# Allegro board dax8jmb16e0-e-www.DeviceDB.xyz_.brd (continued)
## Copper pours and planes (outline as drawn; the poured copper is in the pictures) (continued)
N27265684 on TOP (solid shape): 190.56,30.46 190.56,29.33 190.51,29.28 190.51,28.94 190.5,28.93 190.48,28.81 190.5,28.68 190.51,28.68 190.51,28.33 190.36,28.17 188.7,28.17 188.43,28.45 188.43,30.46 188.44,30.47 188.55,30.5 188.61,30.4 188.61,29.8 188.81,29.8 188.81,30.54 188.83,30.57 188.87,30.59 189.09,30.59 189.11,30.61 190.41,30.61
N27267906 on BOTTOM (solid shape): 14.23,114.97 14.23,113.46 14.67,113.02 14.67,112.52 14.23,112.09 14.23,111.44 14.99,110.67 14.99,109.66 14.89,109.56 14.23,109.56 14.03,109.76 14.03,110.22 12.63,111.61 12.63,111.72 12.63,112.02 13.15,112.54 13.15,113.33 13.1,113.38 12.72,113.38 12.63,113.47 12.63,114.05 12.71,114.13 13.06,114.13 13.32,114.38 13.32,115.02 13.5,115.19 14,115.19
N27303100 on TOP (solid shape): 153.6,34.3 153.6,34.25 153.63,34.23 153.63,33.69 153.68,33.63 153.68,33.51 153.71,33.4 153.82,33.31 153.83,33.28 153.83,32.16 153.75,32.09 153.7,32.07 153.67,32.12 153.67,32.85 153.47,32.85 153.47,32.11 153.45,32.07 153.42,32.06 152.36,32.06 151.7,31.4 151.7,31.34 151.5,31.15 150.76,31.15 150.63,31.27 149.84,31.27 149.67,31.45 149.67,32.34 150.1,32.77 151.24,32.77 151.8,33.33 151.8,34.04 151.65,34.19 151.65,35.36 151.71,35.43 152.47,35.43
N27303319 on TOP (solid shape): 157.68,34.66 157.68,33.81 158,33.5 158,31.55 157.92,31.48 157.48,31.48 157.24,31.71 157.24,32.1 157.06,32.29 156.57,32.29 156.32,32.03 156.22,32.04 156.17,32.03 155.72,32.03 155.68,32.05 155.67,32.09 155.67,32.85 155.47,32.85 155.47,32.09 155.45,32.05 155.42,32.03 155.33,32.03 155.28,32.09 155.28,33.2 155.76,33.69 156.5,33.69 156.76,33.95 156.76,34.66 156.93,34.83 157.51,34.83
N30957248 on TOP (solid shape): 34.1,125.36 34.1,124.41 33.96,124.28 32.62,124.28 31.93,123.6 31.32,123.6 31.2,123.71 31.2,124.36 32.24,125.41 32.24,125.41 32.39,125.55 33.9,125.55
N31445230 on BOTTOM (solid shape): 223.78,74.94 223.78,73.97 223.43,73.61 223.43,72.04 224.07,71.39 224.07,70.87 224.38,70.57 224.38,70.4 224.39,70.39 224.39,68.47 224.39,62.01 224.16,61.78 221.55,61.78 221.39,61.93 221.39,63.82 221.46,63.96 221.47,64.12 221.47,64.13 221.48,64.15 221.83,64.5 223.43,64.5 223.76,64.83 223.76,69.75 223.63,69.88 223.63,70.52 223.32,70.83 223.32,70.99 223.25,71.36 222.89,71.47 222.89,71.96 222.91,72 223.01,72.14 223.04,72.31 223.04,72.54 223.03,72.67 222.97,72.78 222.96,72.81 222.97,72.84 223.04,73.12 222.91,73.39 222.89,73.42 222.89,73.94 223.12,74.17 223.12,74.41 223.12,74.96 223.25,75.09 223.63,75.09
N31667829 on TOP (solid shape): 162.67,31.78 162.67,29.39 162.34,29.06 159.16,29.06 158.97,29.26 158.97,30.22 159.37,30.61 159.37,31.76 159.72,32.11 162.34,32.11
N31667829 on BOTTOM (solid shape): 161.31,34.96 161.32,34.95 161.6,34.8 161.89,34.95 161.9,34.96 161.94,34.98 163.58,34.98 163.86,34.7 163.86,31.71 163.86,31.68 163.86,31.38 163.86,31.29 163.78,31.21 163.12,31.21 163.02,31.11 163.02,30.38 162.87,30.23 157.72,30.23 157.26,30.69 157.26,31.18 157.27,31.24 157.26,31.31 157.26,34.75 157.49,34.98 161.27,34.98
N31667845 on BOTTOM (solid shape): 164.68,27.13 164.68,25.43 164.6,25.35 164.02,25.35 163.71,25.66 163.71,27.54 163.89,27.72 164.09,27.72
N31667871 on TOP (solid shape): 159.27,24.92 159.27,23.81 159.09,23.63 159.09,23.14 159,23.06 158.31,23.06 158.22,23.14 158.22,24.72 158.48,24.97 159.22,24.97
N32485094 on TOP (solid shape): 221.94,102.65 221.94,102.13 221.85,102.04 220.1,102.04 220.05,102.09 220.05,102.7 220.15,102.8 221.79,102.8
N36756780 on BOTTOM (solid shape): 152.31,18.37 152.31,17.4 152.1,17.2 150,17.2 149.87,17.33 149.87,18.37 150,18.5 152.18,18.5
N37057994 on BOTTOM (solid shape): outline of 137 points within 133.89,108.92 139.7,112.93
N37096667 on TOP (solid shape): 202.37,84.51 202.57,84.3 202.57,83.83 202.24,83.5 200.59,83.5 200.49,83.6 200.49,84.13 200.59,84.23 200.85,84.21 201.1,84.23 201.28,84.41 201.28,84.61 201.46,84.79 202.37,84.79
N38167474 on TOP (solid shape): 42.07,125.5 42.07,124.2 42.04,124.19 41.87,124.06 41.8,123.86 41.8,123.84 41.61,123.65 39.18,123.65 38.92,123.91 38.92,125.53 39.07,125.68 39.28,125.68 39.38,125.68 39.39,125.7 41.87,125.7
N38167474 on TOP (solid shape): 25.49,126.62 25.51,126.59 25.5,126.56 25.73,126.03 26.16,126.41 26.19,126.49 26.27,126.52 26.32,126.52 26.6,126.24 26.6,125.71 26.48,125.58 26.25,125.58 25.92,125.25 25.43,125.25 25.07,125.61 24.64,125.61 24.55,125.53 23.76,125.53 23.68,125.61 23.68,126.7 23.78,126.8 25.31,126.8
N38167474 on IN1 (solid shape): outline of 337 points within 25.56,121.75 41.77,126.16
N38256936 on TOP (solid shape): 41.74,34.3 41.74,33.36 42.05,33.05 42.25,33.05 42.28,33.04 42.3,33 42.3,31.81 42.25,31.76 41.66,31.76 40.27,33.14 40.27,33.33 39.91,33.69 39.91,34.3 40.14,34.52 41.51,34.52
N38936280 on TOP (solid shape): 124.67,28.83 124.67,27.84 123.96,27.13 123.6,27.13 123.13,26.66 121.74,26.66 121.52,26.45 121.52,25.61 122.18,24.95 123.45,24.95 123.66,24.74 123.66,23.83 123.53,23.7 120.99,23.7 120.38,24.31 120.38,27.36 120.79,27.77 122.94,27.77 123.12,27.95 123.12,28.31 123.13,28.32 123.15,28.45 123.13,28.57 123.12,28.58 123.12,28.71 123.45,29.04 124.47,29.04
N38936318 on BOTTOM (solid shape): 122.82,25.94 122.81,25.73 122.81,25.55 121.97,24.71 121.97,24.07 121.85,23.96 121.27,23.96 120.95,24.27 120.95,24.4 120.94,24.41 120.94,24.97 122.03,26.07 122.69,26.07
N38936359 on TOP (solid shape): 114.49,28.12 114.49,27.56 114.28,27.36 112.66,27.36 112.53,27.49 112.53,28.25 112.66,28.38 114.23,28.38
N39109711 on TOP (solid shape): 178.19,34.93 178.19,34.93 178.68,34.45 179.54,34.45 179.66,34.32 179.66,33.7 179.53,33.57 178.54,33.57 177.87,32.9 175.95,32.9 175.93,32.91 175.91,32.92 175.67,33.1 175.39,33.04 175.33,33.03 175.31,33.08 175.31,33.09 174.72,33.09 174.72,32.95 174.71,32.91 174.67,32.9 173.13,32.9 172.91,33.13 172.91,33.79 173.74,34.63 173.74,35.18 173.95,35.39 177.73,35.39
N39109711 on BOTTOM (solid shape): 181.11,35.18 181.11,34.24 180.27,33.41 180.27,32.52 180.17,32.42 175.99,32.42 175.91,32.47 175.91,32.57 175.62,33.11 175.27,32.61 175.26,32.51 175.18,32.47 175.14,32.47 175.11,32.43 175.06,32.42 175.04,32.42 171.13,32.42 170.85,32.7 170.85,34.38 170.85,34.4 170.86,34.42 170.98,34.7 170.86,34.98 170.85,35 170.85,35.02 170.85,35.21 170.95,35.31 180.98,35.31
N39254281 on TOP (solid shape): 221.78,9.94 221.78,9.1 222.08,8.79 222.08,7.35 221.85,7.12 221.06,7.12 220.91,7.27 220.91,7.91 221.45,8.44 221.45,8.62 220.91,9.15 220.91,10.42 220.98,10.48 221.23,10.48
N39257569 on TOP (solid shape): 222.23,19.16 222.23,17.94 222.11,17.81 222.11,16.83 221.84,16.57 221.61,16.57 221.08,16.03 220.79,16.03 220.49,15.74 220.34,15.74 220.25,15.65 220.25,14.71 220.2,14.66 220.15,14.66 220.1,14.71 220.1,15.75 220.47,16.12 220.47,16.13 221.44,17.11 221.44,18 221.52,18.08 221.52,19.19 221.58,19.25 222.14,19.25
N39257899 on TOP (solid shape): 219.67,25.08 219.67,21.37 220.07,20.96 220.07,20.38 221.17,19.28 221.17,17.13 219.87,15.83 219.87,15.64 219.86,15.63 219.86,14.68 219.85,14.66 219.77,14.66 219.7,14.73 219.7,15.58 219.69,15.6 219.69,16.01 220.4,16.72 220.4,18.65 219.13,19.92 217.99,19.92 217.9,19.83 217.85,19.83 217.52,19.5 217.52,19.16 217.52,19.11 217.52,18.05 217.61,17.96 217.61,16.9 217.77,16.73 217.78,16.72 217.79,16.7 217.79,15.7 217.86,15.63 217.86,14.69 217.84,14.66 217.74,14.66 217.72,14.68 217.72,15.58 217.71,15.6 216.84,16.48 216.84,17.29 216.8,17.33 216.8,18.14 216.93,18.27 216.93,20.36 217.94,21.38 217.94,25 218.17,25.23 219.52,25.23
N39295059 on BOTTOM (solid shape): outline of 124 points within 188.63,29.11 205.09,36.68

Small or netless copper shapes (teardrops, artwork), in the pictures only: 89 on TOP, 44 on BOTTOM, 46 on IN1, 16 on IN2

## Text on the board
Ref Des/Silkscreen Bottom: Copyright 2018 HP  Development Company L P | MODEL:X8J-6L | REV:E | DAX8JMB16E0
User.Comments: PARTITION_2 | 16x35 | 39x110 | 30x32 | 63x83
Ref Des/Silkscreen Top: DAX8JMB16E0 | REV:E
User.8: Power Board | %%uTOP Conponent
User.9: Touchpad | Battery | Speaker | FPR | SSD | HDD | Fan | KB | LVDS | SD Board | 360 Degree | Pin 1 | Backlight | CCG5 | DC-IN | %%uBottom Conponent
User.12: +VCC_CORE | +1.05V_DEEP_SUS | +1.2VSUS | +3V | +5V | +3VPCU | +5VPCU | +VCC_SA | GND | AGND
User.25: %%uTop Height
User.26: %%uBottom Height
User.27: GND | AGND
User.28: GND | AGND
User.29: REV:A-3 | REV:A-15
User.45: PadStack_Check:Oct 11 10:04:03 2018 | TP check:Oct 11 09:51:07 2018 | XY-Check acute:Oct 11 09:56:11 2018 | XY-Create nettxt:Mar 15 16:20:57 2018 | XY-Create plane:May 31 14:29:34 2018 | XY-Cross plane-BOTTOM-SGND:Oct 11 10:00:55 2018 | XY-Cross plane-IN1-SVCC:Oct 11 10:00:37 2018 | XY-Cross plane-IN2-SGND:Oct 11 10:00:49 2018 | XY-Cross plane-TOP-SVCC:Oct 11 10:00:12 2018 | XY-Dxf to pin check:Jun 01 11:18:40 2018 | XY-Etch cross-IN1-IN2:Oct 11 10:00:29 2018 | XY-Etch ref-BOTTOM-SGND:Oct 11 10:01:02 2018 | XY-Etch ref-IN1-SVCC:Oct 11 10:00:48 2018 | XY-Etch ref-IN2-SGND:Oct 11 10:00:54 2018 | XY-Etch ref-TOP-SVCC:Oct 11 10:00:29 2018 | XY-Excess check:Jun 01 10:47:17 2018 | XY-Mask check:Oct 11 10:08:32 2018 | XY-Outline check:Jun 01 11:36:15 2018 | XY-PadStack_Check:Oct 11 10:04:03 2018 | XY-Plane net check:Oct 11 09:52:51 2018 | XY-Prop check:Mar 30 16:21:15 2018 | XY-Symbol cross:Mar 30 16:07:12 2018 | XY-TP check:Oct 11 09:51:07 2018 | XY-shape min check:Oct 11 09:32:15 2018 | XY-shape pin check:Mar 30 16:22:21 2018 | XY-via check:Oct 11 10:04:39 2018 | check acute:Oct 11 09:56:11 2018 | cross plane-BOTTOM-SGND:Oct 11 10:00:55 2018 | cross plane-IN1-SVCC:Oct 11 10:00:37 2018 | cross plane-IN2-SGND:Oct 11 10:00:49 2018 | cross plane-TOP-SVCC:Oct 11 10:00:12 2018 | dxf to pin check:Jun 01 11:18:40 2018 | etch cross-IN1-IN2:Oct 11 10:00:29 2018 | etch ref-BOTTOM-SGND:Oct 11 10:01:02 2018 | etch ref-IN1-SVCC:Oct 11 10:00:48 2018 | etch ref-IN2-SGND:Oct 11 10:00:54 2018 | etch ref-TOP-SVCC:Oct 11 10:00:29 2018 | outline check:Jun 01 11:36:15 2018 | plane net check:Oct 11 09:52:50 2018 | shape min check:Oct 11 09:32:15 2018 | via check:Oct 11 10:04:39 2018 | FIGURE | TYPE | Circle | SIZE | 8.0 | 10.0 | 12.0 | 14.0 | 18.0 | 22.0 | 28.0 | 35.0 | 39.0 | 43.0 | 83.0 | 91.0 | 98.0 | 110.0 | 122.0 | 150.0 | 252.0 | 32.0 | 40.0 | 47.0 | 63.0 | 67.0 | DRILL CHART: TOP to BOTTOM | ALL UNITS ARE IN MILS | PLATED | NON-PLATED | ROTATION | - | QTY | 57 | 5083 | 9 | 8 | 226 | 10 | 19 | 18 | 4 | 1 | 6 | 3 | 2 | 5485 | Oblong | 43.0x20.0 | 55.0x24.0 | 59.0x20.0 | 59.0x35.0 | 63.0x35.0 | 75.0x35.0 | 79.0x24.0 | 79.0x35.0 | 122.0x83.0 | 189.0x91.0 | 90.000 | 0.000 | 38 | TOTAL HOLES:
